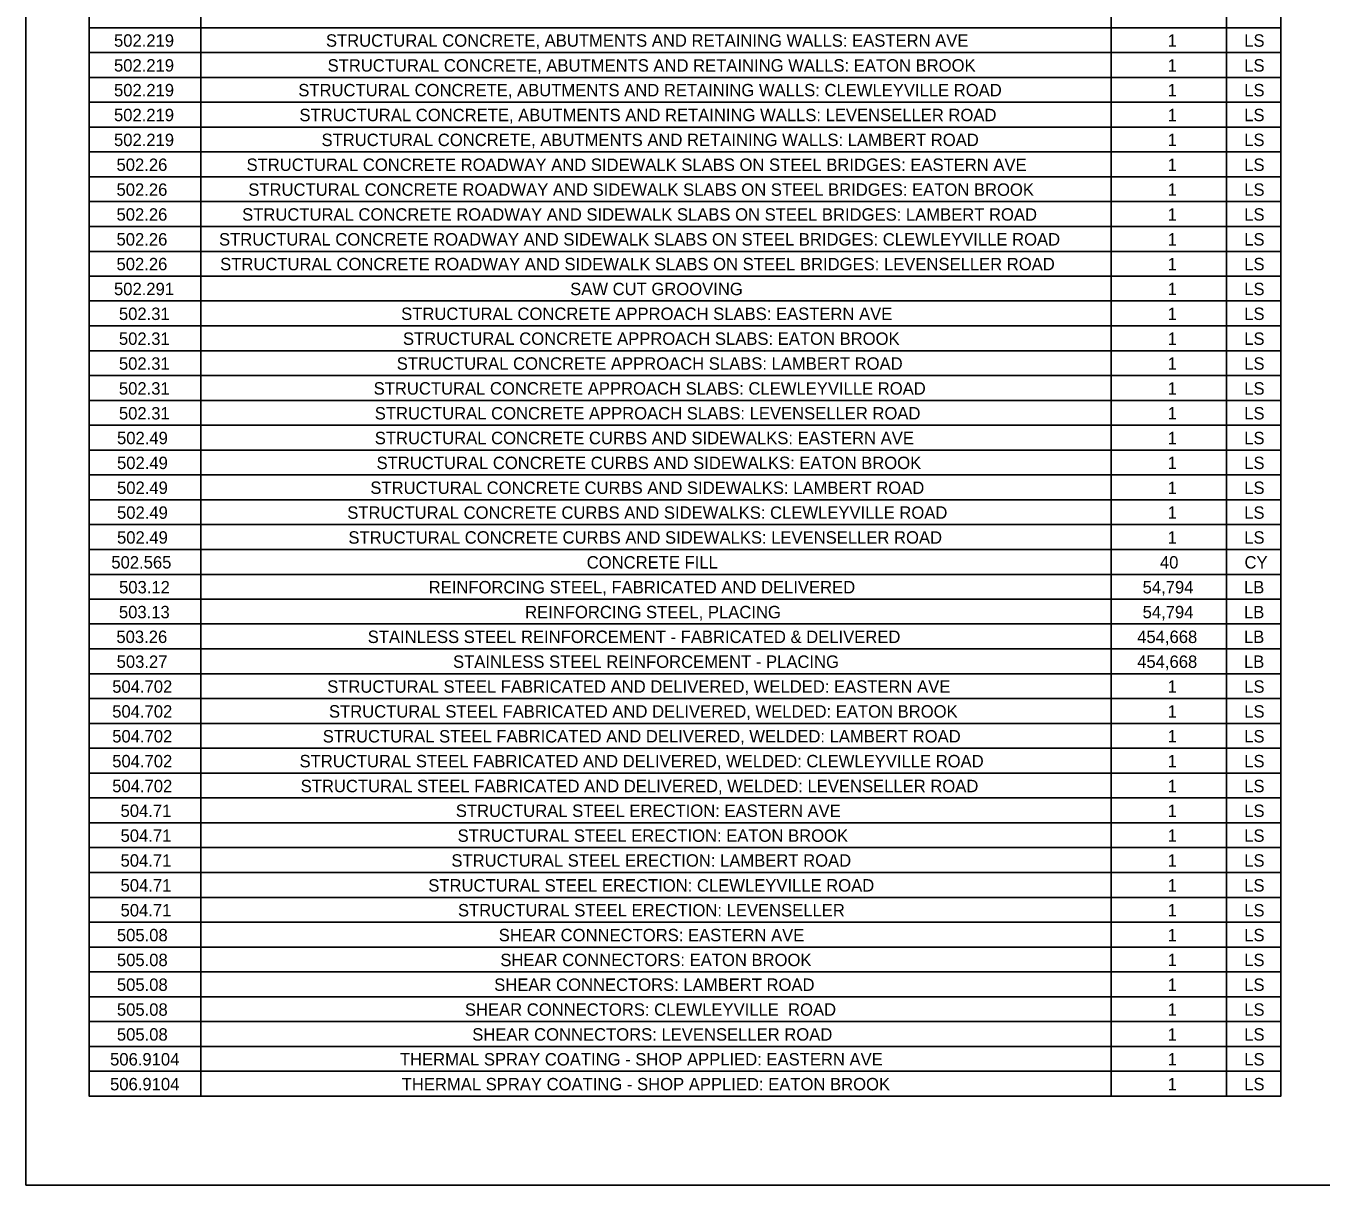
# Model space of a CAD drawing. Extents: x -18.7 to 5.6, y -2.7 to 5.1.
# Drawn here: x -17.663 to -16.637, y 2.172 to 3.09 of the extents above; entities that cross this region are included whole.
import ezdxf

# ---------------------------------------------------------------- set-up
doc = ezdxf.new("R2010")
doc.units = 0
doc.layers.add('ANNOTATION', color=7, linetype='Continuous')
doc.layers.add('BORDER', color=7, linetype='Continuous')

msp = doc.modelspace()

# ---------------------------------------------------------------- linework, layer by layer
at = {"layer": 'ANNOTATION'}
msp.add_lwpolyline([(-17.663, 4.0141), (-13.3075, 4.0141), (-13.3075, 2.1719), (-17.663, 2.1719)], close=True, dxfattribs=at)
at = {"layer": 'BORDER'}
for p, q in [((-17.5245, 3.9551), (-17.5245, 2.2424)), ((-16.8032, 3.9551), (-16.8032, 2.2424)), ((-16.7118, 3.9551), (-16.7118, 2.2424)), ((-17.613, 3.0889), (-16.6688, 3.0889)), ((-17.613, 3.0692), (-16.6688, 3.0692)), ((-17.613, 3.0495), (-16.6688, 3.0495)), ((-17.613, 3.0299), (-16.6688, 3.0299)), ((-17.613, 3.0102), (-16.6688, 3.0102)), ((-17.613, 2.9905), (-16.6688, 2.9905)), ((-17.613, 2.9708), (-16.6688, 2.9708)), ((-17.613, 2.9511), (-16.6688, 2.9511)), ((-17.613, 2.9314), (-16.6688, 2.9314)), ((-17.613, 2.9117), (-16.6688, 2.9117)), ((-17.613, 2.8921), (-16.6688, 2.8921)), ((-17.613, 2.8724), (-16.6688, 2.8724)), ((-17.613, 2.8527), (-16.6688, 2.8527)), ((-17.613, 2.833), (-16.6688, 2.833)), ((-17.613, 2.8133), (-16.6688, 2.8133)), ((-17.613, 2.7936), (-16.6688, 2.7936)), ((-17.613, 2.7739), (-16.6688, 2.7739)), ((-17.613, 2.7543), (-16.6688, 2.7543)), ((-17.613, 2.7346), (-16.6688, 2.7346)), ((-17.613, 2.7149), (-16.6688, 2.7149)), ((-17.613, 2.6952), (-16.6688, 2.6952)), ((-17.613, 2.6755), (-16.6688, 2.6755)), ((-17.613, 2.6558), (-16.6688, 2.6558)), ((-17.613, 2.6361), (-16.6688, 2.6361)), ((-17.613, 2.6165), (-16.6688, 2.6165)), ((-17.613, 2.5968), (-16.6688, 2.5968)), ((-17.613, 2.5771), (-16.6688, 2.5771)), ((-17.613, 2.5574), (-16.6688, 2.5574)), ((-17.613, 2.5377), (-16.6688, 2.5377)), ((-17.613, 2.518), (-16.6688, 2.518)), ((-17.613, 2.4983), (-16.6688, 2.4983)), ((-17.613, 2.4787), (-16.6688, 2.4787)), ((-17.613, 2.459), (-16.6688, 2.459)), ((-17.613, 2.4393), (-16.6688, 2.4393)), ((-17.613, 2.4196), (-16.6688, 2.4196)), ((-17.613, 2.3999), (-16.6688, 2.3999)), ((-17.613, 2.3802), (-16.6688, 2.3802)), ((-17.613, 2.3605), (-16.6688, 2.3605)), ((-17.613, 2.3408), (-16.6688, 2.3408)), ((-17.613, 2.3212), (-16.6688, 2.3212)), ((-17.613, 2.3015), (-16.6688, 2.3015)), ((-17.613, 2.2818), (-16.6688, 2.2818)), ((-17.613, 2.2621), (-16.6688, 2.2621)), ((-17.613, 2.2424), (-16.6688, 2.2424))]:
    msp.add_line(p, q, dxfattribs=at)
msp.add_lwpolyline([(-17.613, 3.9748), (-16.6688, 3.9748), (-16.6688, 2.2424), (-17.613, 2.2424)], close=True, dxfattribs=at)

# ---------------------------------------------------------------- texts
at = {"layer": 'ANNOTATION'}
for s, height, p in [('502.219', 0.00984, (-17.5932, 3.0738)), ('STRUCTURAL CONCRETE, ABUTMENTS AND RETAINING WALLS: EASTERN AVE', 0.009843, (-17.4253, 3.0738)), ('1', 0.00984, (-16.7585, 3.0738)), ('LS', 0.00984, (-16.6978, 3.0738)), ('502.219', 0.00984, (-17.5932, 3.0541)), ('STRUCTURAL CONCRETE, ABUTMENTS AND RETAINING WALLS: EATON BROOK', 0.009843, (-17.424, 3.0541)), ('1', 0.00984, (-16.7585, 3.0541)), ('LS', 0.00984, (-16.6978, 3.0541)), ('502.219', 0.00984, (-17.5932, 3.0345)), ('STRUCTURAL CONCRETE, ABUTMENTS AND RETAINING WALLS: CLEWLEYVILLE ROAD', 0.009843, (-17.4472, 3.0345)), ('1', 0.00984, (-16.7585, 3.0345)), ('LS', 0.00984, (-16.6978, 3.0345)), ('502.219', 0.00984, (-17.5932, 3.0148)), ('STRUCTURAL CONCRETE, ABUTMENTS AND RETAINING WALLS: LEVENSELLER ROAD', 0.009843, (-17.4463, 3.0148)), ('1', 0.00984, (-16.7585, 3.0148)), ('LS', 0.00984, (-16.6978, 3.0148)), ('502.219', 0.00984, (-17.5932, 2.9951)), ('STRUCTURAL CONCRETE, ABUTMENTS AND RETAINING WALLS: LAMBERT ROAD', 0.009843, (-17.4288, 2.9951)), ('1', 0.00984, (-16.7585, 2.9951)), ('LS', 0.00984, (-16.6978, 2.9951)), ('502.26', 0.00984, (-17.5912, 2.9754)), ('STRUCTURAL CONCRETE ROADWAY AND SIDEWALK SLABS ON STEEL BRIDGES: EASTERN AVE', 0.009843, (-17.4882, 2.9754)), ('1', 0.00984, (-16.7585, 2.9754)), ('LS', 0.00984, (-16.6978, 2.9754)), ('502.26', 0.00984, (-17.5912, 2.9557)), ('STRUCTURAL CONCRETE ROADWAY AND SIDEWALK SLABS ON STEEL BRIDGES: EATON BROOK', 0.009843, (-17.4868, 2.9557)), ('1', 0.00984, (-16.7585, 2.9557)), ('LS', 0.00984, (-16.6978, 2.9557)), ('502.26', 0.00984, (-17.5912, 2.936)), ('STRUCTURAL CONCRETE ROADWAY AND SIDEWALK SLABS ON STEEL BRIDGES: LAMBERT ROAD', 0.009843, (-17.4917, 2.936)), ('1', 0.00984, (-16.7585, 2.936)), ('LS', 0.00984, (-16.6978, 2.936)), ('502.26', 0.00984, (-17.5912, 2.9163)), ('STRUCTURAL CONCRETE ROADWAY AND SIDEWALK SLABS ON STEEL BRIDGES: CLEWLEYVILLE ROAD', 0.009843, (-17.51, 2.9163)), ('1', 0.00984, (-16.7585, 2.9163)), ('LS', 0.00984, (-16.6978, 2.9163)), ('502.26', 0.00984, (-17.5912, 2.8967)), ('STRUCTURAL CONCRETE ROADWAY AND SIDEWALK SLABS ON STEEL BRIDGES: LEVENSELLER ROAD', 0.009843, (-17.5091, 2.8967)), ('1', 0.00984, (-16.7585, 2.8967)), ('LS', 0.00984, (-16.6978, 2.8967)), ('502.291', 0.00984, (-17.5932, 2.877)), ('SAW CUT GROOVING', 0.009843, (-17.2318, 2.877)), ('1', 0.00984, (-16.7585, 2.877)), ('LS', 0.00984, (-16.6978, 2.877)), ('502.31', 0.00984, (-17.5893, 2.8573)), ('STRUCTURAL CONCRETE APPROACH SLABS: EASTERN AVE', 0.009843, (-17.3657, 2.8573)), ('1', 0.00984, (-16.7585, 2.8573)), ('LS', 0.00984, (-16.6978, 2.8573)), ('502.31', 0.00984, (-17.5893, 2.8376)), ('STRUCTURAL CONCRETE APPROACH SLABS: EATON BROOK', 0.009843, (-17.3643, 2.8376)), ('1', 0.00984, (-16.7585, 2.8376)), ('LS', 0.00984, (-16.6978, 2.8376)), ('502.31', 0.00984, (-17.5893, 2.8179)), ('STRUCTURAL CONCRETE APPROACH SLABS: LAMBERT ROAD', 0.009843, (-17.3692, 2.8179)), ('1', 0.00984, (-16.7585, 2.8179)), ('LS', 0.00984, (-16.6978, 2.8179)), ('502.31', 0.00984, (-17.5893, 2.7982)), ('STRUCTURAL CONCRETE APPROACH SLABS: CLEWLEYVILLE ROAD', 0.009843, (-17.3875, 2.7982)), ('1', 0.00984, (-16.7585, 2.7982)), ('LS', 0.00984, (-16.6978, 2.7982)), ('502.31', 0.00984, (-17.5893, 2.7785)), ('STRUCTURAL CONCRETE APPROACH SLABS: LEVENSELLER ROAD', 0.009843, (-17.3866, 2.7785)), ('1', 0.00984, (-16.7585, 2.7785)), ('LS', 0.00984, (-16.6978, 2.7785)), ('502.49', 0.00984, (-17.5908, 2.7589)), ('STRUCTURAL CONCRETE CURBS AND SIDEWALKS: EASTERN AVE', 0.009843, (-17.3866, 2.7589)), ('1', 0.00984, (-16.7585, 2.7589)), ('LS', 0.00984, (-16.6978, 2.7589)), ('502.49', 0.00984, (-17.5908, 2.7392)), ('STRUCTURAL CONCRETE CURBS AND SIDEWALKS: EATON BROOK', 0.009843, (-17.3852, 2.7392)), ('1', 0.00984, (-16.7585, 2.7392)), ('LS', 0.00984, (-16.6978, 2.7392)), ('502.49', 0.00984, (-17.5908, 2.7195)), ('STRUCTURAL CONCRETE CURBS AND SIDEWALKS: LAMBERT ROAD', 0.009843, (-17.3901, 2.7195)), ('LS', 0.00984, (-16.6978, 2.7195)), ('1', 0.00984, (-16.7585, 2.7195)), ('502.49', 0.00984, (-17.5908, 2.6998)), ('STRUCTURAL CONCRETE CURBS AND SIDEWALKS: CLEWLEYVILLE ROAD', 0.009843, (-17.4084, 2.6998)), ('1', 0.00984, (-16.7585, 2.6998)), ('LS', 0.00984, (-16.6978, 2.6998)), ('502.49', 0.00984, (-17.5908, 2.6801)), ('STRUCTURAL CONCRETE CURBS AND SIDEWALKS: LEVENSELLER ROAD', 0.009843, (-17.4075, 2.6801)), ('1', 0.00984, (-16.7585, 2.6801)), ('LS', 0.00984, (-16.6978, 2.6801)), ('502.565', 0.00984, (-17.5953, 2.6604)), ('CONCRETE FILL', 0.009843, (-17.2187, 2.6604)), ('40', 0.00984, (-16.7646, 2.6604)), ('CY', 0.00984, (-16.6976, 2.6604)), ('503.12', 0.00984, (-17.5892, 2.6407)), ('REINFORCING STEEL, FABRICATED AND DELIVERED', 0.009843, (-17.3439, 2.6407)), ('54,794', 0.00984, (-16.7783, 2.6407)), ('LB', 0.00984, (-16.698, 2.6407)), ('503.13', 0.00984, (-17.5893, 2.621)), ('REINFORCING STEEL, PLACING', 0.009843, (-17.2675, 2.621)), ('54,794', 0.00984, (-16.7783, 2.621)), ('LB', 0.00984, (-16.698, 2.621)), ('503.26', 0.00984, (-17.5913, 2.6014)), ('STAINLESS STEEL REINFORCEMENT - FABRICATED & DELIVERED', 0.009843, (-17.3922, 2.6014)), ('454,668', 0.00984, (-16.7826, 2.6014)), ('LB', 0.00984, (-16.698, 2.6014)), ('503.27', 0.00984, (-17.5911, 2.5817)), ('STAINLESS STEEL REINFORCEMENT - PLACING', 0.009843, (-17.3246, 2.5817)), ('454,668', 0.00984, (-16.7826, 2.5817)), ('LB', 0.00984, (-16.698, 2.5817)), ('504.702', 0.00984, (-17.5946, 2.562)), ('STRUCTURAL STEEL FABRICATED AND DELIVERED, WELDED: EASTERN AVE', 0.009843, (-17.4243, 2.562)), ('1', 0.00984, (-16.7585, 2.562)), ('LS', 0.00984, (-16.6978, 2.562)), ('504.702', 0.00984, (-17.5946, 2.5423)), ('STRUCTURAL STEEL FABRICATED AND DELIVERED, WELDED: EATON BROOK', 0.009843, (-17.4229, 2.5423)), ('1', 0.00984, (-16.7585, 2.5423)), ('LS', 0.00984, (-16.6978, 2.5423)), ('504.702', 0.00984, (-17.5946, 2.5226)), ('STRUCTURAL STEEL FABRICATED AND DELIVERED, WELDED: LAMBERT ROAD', 0.009843, (-17.4278, 2.5226)), ('1', 0.00984, (-16.7585, 2.5226)), ('LS', 0.00984, (-16.6978, 2.5226)), ('504.702', 0.00984, (-17.5946, 2.5029)), ('STRUCTURAL STEEL FABRICATED AND DELIVERED, WELDED: CLEWLEYVILLE ROAD', 0.009843, (-17.4462, 2.5029)), ('1', 0.00984, (-16.7585, 2.5029)), ('LS', 0.00984, (-16.6978, 2.5029)), ('504.702', 0.00984, (-17.5946, 2.4832)), ('STRUCTURAL STEEL FABRICATED AND DELIVERED, WELDED: LEVENSELLER ROAD', 0.009843, (-17.4453, 2.4832)), ('1', 0.00984, (-16.7585, 2.4832)), ('LS', 0.00984, (-16.6978, 2.4832)), ('504.71', 0.00984, (-17.588, 2.4636)), ('STRUCTURAL STEEL ERECTION: EASTERN AVE', 0.009843, (-17.3224, 2.4636)), ('1', 0.00984, (-16.7585, 2.4636)), ('LS', 0.00984, (-16.6978, 2.4636)), ('504.71', 0.00984, (-17.588, 2.4439)), ('STRUCTURAL STEEL ERECTION: EATON BROOK', 0.009843, (-17.321, 2.4439)), ('1', 0.00984, (-16.7585, 2.4439)), ('LS', 0.00984, (-16.6978, 2.4439)), ('504.71', 0.00984, (-17.588, 2.4242)), ('STRUCTURAL STEEL ERECTION: LAMBERT ROAD', 0.009843, (-17.3259, 2.4242)), ('1', 0.00984, (-16.7585, 2.4242)), ('LS', 0.00984, (-16.6978, 2.4242)), ('504.71', 0.00984, (-17.588, 2.4045)), ('STRUCTURAL STEEL ERECTION: CLEWLEYVILLE ROAD', 0.009843, (-17.3442, 2.4045)), ('1', 0.00984, (-16.7585, 2.4045)), ('LS', 0.00984, (-16.6978, 2.4045)), ('504.71', 0.00984, (-17.588, 2.3848)), ('STRUCTURAL STEEL ERECTION: LEVENSELLER', 0.009843, (-17.3207, 2.3848)), ('1', 0.00984, (-16.7585, 2.3848)), ('LS', 0.00984, (-16.6978, 2.3848)), ('505.08', 0.00984, (-17.5909, 2.3651)), ('SHEAR CONNECTORS: EASTERN AVE', 0.009843, (-17.2884, 2.3651)), ('1', 0.00984, (-16.7585, 2.3651)), ('LS', 0.00984, (-16.6978, 2.3651)), ('505.08', 0.00984, (-17.5909, 2.3454)), ('SHEAR CONNECTORS: EATON BROOK', 0.009843, (-17.2871, 2.3454)), ('1', 0.00984, (-16.7585, 2.3454)), ('LS', 0.00984, (-16.6978, 2.3454)), ('505.08', 0.00984, (-17.5909, 2.3258)), ('SHEAR CONNECTORS: LAMBERT ROAD', 0.009843, (-17.292, 2.3258)), ('1', 0.00984, (-16.7585, 2.3258)), ('LS', 0.00984, (-16.6978, 2.3258)), ('505.08', 0.00984, (-17.5909, 2.3061)), ('SHEAR CONNECTORS: CLEWLEYVILLE  ROAD', 0.009843, (-17.3152, 2.3061)), ('1', 0.00984, (-16.7585, 2.3061)), ('LS', 0.00984, (-16.6978, 2.3061)), ('505.08', 0.00984, (-17.5909, 2.2864)), ('SHEAR CONNECTORS: LEVENSELLER ROAD', 0.009843, (-17.3094, 2.2864)), ('1', 0.00984, (-16.7585, 2.2864)), ('LS', 0.00984, (-16.6978, 2.2864)), ('506.9104', 0.00984, (-17.5963, 2.2667)), ('THERMAL SPRAY COATING - SHOP APPLIED: EASTERN AVE', 0.009843, (-17.3667, 2.2667)), ('1', 0.00984, (-16.7585, 2.2667)), ('LS', 0.00984, (-16.6978, 2.2667)), ('506.9104', 0.00984, (-17.5963, 2.247)), ('THERMAL SPRAY COATING - SHOP APPLIED: EATON BROOK', 0.009843, (-17.3653, 2.247)), ('1', 0.00984, (-16.7585, 2.247)), ('LS', 0.00984, (-16.6978, 2.247))]:
    msp.add_text(s, height=height, dxfattribs=at).set_placement(p)

doc.saveas('drawing.dxf')
